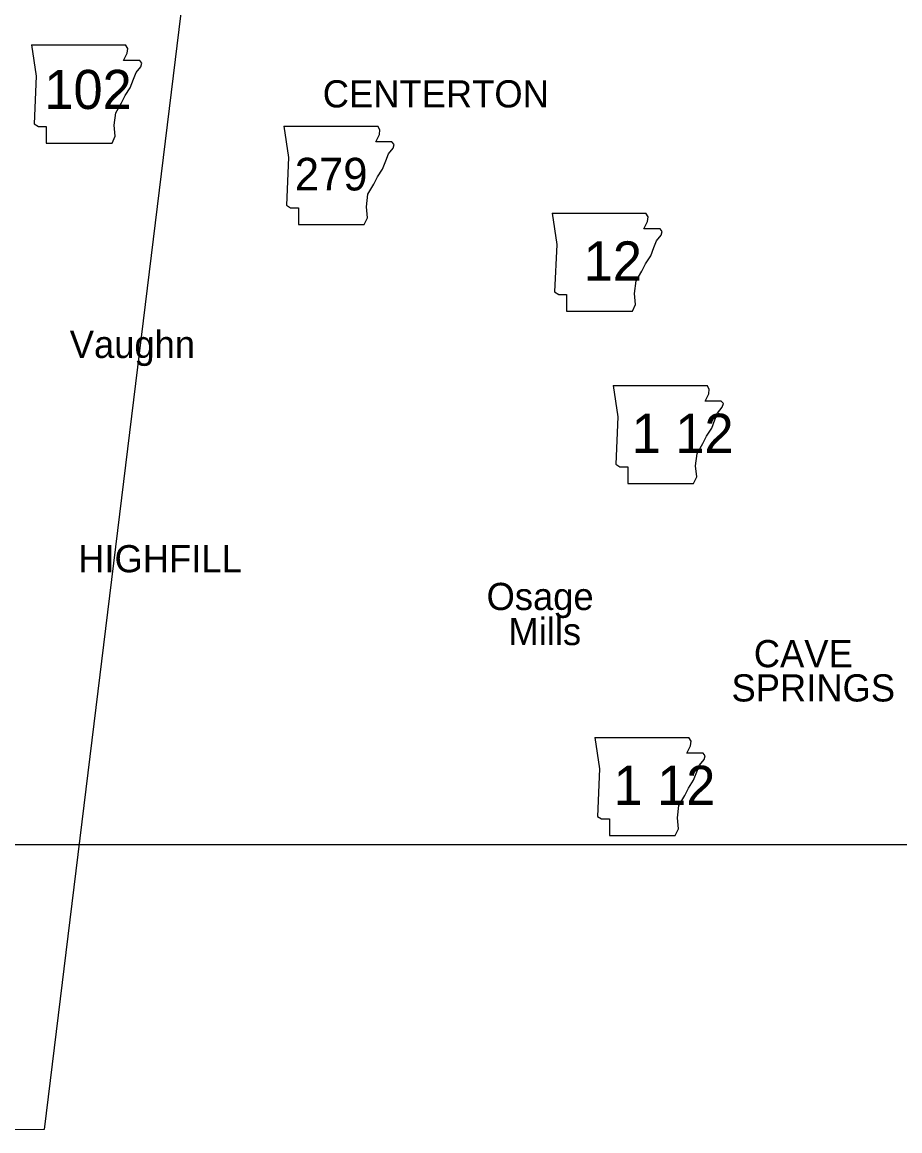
# Model space of a CAD drawing. Extents: x 6028647 to 6035072, y 5366486 to 5368495.
# Drawn here: x 6028934.9 to 6029148, y 5367846.9 to 5368116.1 of the extents above; entities that cross this region are included whole.
import ezdxf

# ---------------------------------------------------------------- set-up
doc = ezdxf.new("R2010")
doc.units = 0
for name, color, linetype in [('21', 7, 'Continuous'), ('24', 7, 'Continuous'), ('25', 7, 'Continuous'), ('Default', 7, 'Continuous'), ('R_NoPlot', 7, 'Continuous')]:
    doc.layers.add(name, color=color, linetype=linetype)

msp = doc.modelspace()

# ---------------------------------------------------------------- linework, layer by layer
at = {"layer": '21'}
for p, q in [((6028937.17, 5368110.57), (6028938.32, 5368102.95)), ((6028960.52, 5368109.68), (6028960, 5368110.56)), ((6028959.51, 5368106.76), (6028960.39, 5368108.54)), ((6028960.39, 5368108.54), (6028960.52, 5368109.68)), ((6028963.44, 5368106.76), (6028959.51, 5368106.76)), ((6028962.55, 5368103.84), (6028963.69, 5368105.24)), ((6028963.95, 5368106.13), (6028963.44, 5368106.76)), ((6028963.69, 5368105.24), (6028963.95, 5368106.13)), ((6028938.32, 5368102.95), (6028937.81, 5368091.41)), ((6028961.16, 5368100.16), (6028961.92, 5368102.19)), ((6028961.92, 5368102.19), (6028962.55, 5368103.84)), ((6028959.89, 5368098.26), (6028961.16, 5368100.16)), ((6028957.6, 5368094.07), (6028959, 5368096.48)), ((6028959, 5368096.48), (6028959.89, 5368098.26)), ((6028957.22, 5368091.03), (6028957.6, 5368094.07)), ((6028937.81, 5368091.41), (6028938.82, 5368090.77)), ((6028957.48, 5368088.36), (6028957.22, 5368091.03)), ((6028938.82, 5368090.77), (6028940.73, 5368090.77)), ((6028940.73, 5368090.77), (6028940.73, 5368086.71)), ((6028956.71, 5368086.71), (6028957.48, 5368088.36)), ((6028998.44, 5368090.8), (6028999.58, 5368083.19)), ((6029020.77, 5368087), (6029021.66, 5368088.77)), ((6029021.78, 5368089.91), (6029021.26, 5368090.79)), ((6029021.66, 5368088.77), (6029021.78, 5368089.91)), ((6028940.73, 5368086.71), (6028956.71, 5368086.71)), ((6029024.7, 5368087), (6029020.77, 5368087)), ((6029025.21, 5368086.36), (6029024.7, 5368087)), ((6029024.96, 5368085.47), (6029025.21, 5368086.36)), ((6028999.58, 5368083.19), (6028999.07, 5368071.64)), ((6029023.18, 5368082.43), (6029023.82, 5368084.08)), ((6029023.82, 5368084.08), (6029024.96, 5368085.47)), ((6029021.15, 5368078.49), (6029022.42, 5368080.4)), ((6029022.42, 5368080.4), (6029023.18, 5368082.43)), ((6029020.26, 5368076.72), (6029021.15, 5368078.49)), ((6029018.87, 5368074.31), (6029020.26, 5368076.72)), ((6029018.49, 5368071.26), (6029018.87, 5368074.31)), ((6028999.07, 5368071.64), (6029000.09, 5368071.01)), ((6029000.09, 5368071.01), (6029001.99, 5368071.01)), ((6029001.99, 5368071.01), (6029001.99, 5368066.95)), ((6029018.74, 5368068.6), (6029018.49, 5368071.26)), ((6029063.57, 5368069.72), (6029064.71, 5368062.11)), ((6029086.92, 5368068.83), (6029086.39, 5368069.71)), ((6029001.99, 5368066.95), (6029017.98, 5368066.95)), ((6029017.98, 5368066.95), (6029018.74, 5368068.6)), ((6029085.9, 5368065.91), (6029086.79, 5368067.69)), ((6029086.79, 5368067.69), (6029086.92, 5368068.83)), ((6029089.84, 5368065.91), (6029085.9, 5368065.91)), ((6029088.95, 5368063), (6029090.09, 5368064.39)), ((6029090.35, 5368065.28), (6029089.84, 5368065.91)), ((6029090.09, 5368064.39), (6029090.35, 5368065.28)), ((6029064.71, 5368062.11), (6029064.21, 5368050.56)), ((6029088.31, 5368061.35), (6029088.95, 5368063)), ((6029086.28, 5368057.41), (6029087.55, 5368059.32)), ((6029087.55, 5368059.32), (6029088.31, 5368061.35)), ((6029085.4, 5368055.64), (6029086.28, 5368057.41)), ((6029084, 5368053.23), (6029085.4, 5368055.64)), ((6029083.62, 5368050.18), (6029084, 5368053.23)), ((6029064.21, 5368050.56), (6029065.22, 5368049.93)), ((6029065.22, 5368049.93), (6029067.13, 5368049.93)), ((6029067.13, 5368049.93), (6029067.13, 5368045.87)), ((6029083.87, 5368047.52), (6029083.62, 5368050.18)), ((6029067.13, 5368045.87), (6029083.11, 5368045.87)), ((6029083.11, 5368045.87), (6029083.87, 5368047.52)), ((6029078.4, 5368027.89), (6029079.55, 5368020.27)), ((6029101.75, 5368027), (6029101.22, 5368027.88)), ((6029101.62, 5368025.86), (6029101.75, 5368027)), ((6029100.74, 5368024.08), (6029101.62, 5368025.86)), ((6029104.67, 5368024.08), (6029100.74, 5368024.08)), ((6029105.18, 5368023.45), (6029104.67, 5368024.08)), ((6029103.15, 5368019.51), (6029103.78, 5368021.16)), ((6029103.78, 5368021.16), (6029104.92, 5368022.56)), ((6029104.92, 5368022.56), (6029105.18, 5368023.45)), ((6029079.55, 5368020.27), (6029079.04, 5368008.73)), ((6029102.39, 5368017.48), (6029103.15, 5368019.51)), ((6029101.12, 5368015.58), (6029102.39, 5368017.48)), ((6029098.83, 5368011.39), (6029100.23, 5368013.8)), ((6029100.23, 5368013.8), (6029101.12, 5368015.58)), ((6029098.45, 5368008.35), (6029098.83, 5368011.39)), ((6029079.04, 5368008.73), (6029080.05, 5368008.09)), ((6029080.05, 5368008.09), (6029081.96, 5368008.09)), ((6029081.96, 5368008.09), (6029081.96, 5368004.03)), ((6029098.71, 5368005.68), (6029098.45, 5368008.35)), ((6029097.94, 5368004.03), (6029098.71, 5368005.68)), ((6029081.96, 5368004.03), (6029097.94, 5368004.03)), ((6029073.98, 5367942.43), (6029075.12, 5367934.82)), ((6029096.31, 5367938.62), (6029097.2, 5367940.4)), ((6029097.33, 5367941.54), (6029096.8, 5367942.42)), ((6029097.2, 5367940.4), (6029097.33, 5367941.54)), ((6029100.25, 5367938.62), (6029096.31, 5367938.62)), ((6029100.75, 5367937.99), (6029100.25, 5367938.62)), ((6029100.5, 5367937.1), (6029100.75, 5367937.99)), ((6029098.72, 5367934.06), (6029099.36, 5367935.71)), ((6029099.36, 5367935.71), (6029100.5, 5367937.1)), ((6029075.12, 5367934.82), (6029074.62, 5367923.27)), ((6029097.96, 5367932.03), (6029098.72, 5367934.06)), ((6029095.81, 5367928.35), (6029096.69, 5367930.12)), ((6029096.69, 5367930.12), (6029097.96, 5367932.03)), ((6029094.41, 5367925.94), (6029095.81, 5367928.35)), ((6029094.03, 5367922.89), (6029094.41, 5367925.94)), ((6029074.62, 5367923.27), (6029075.63, 5367922.64)), ((6029075.63, 5367922.64), (6029077.53, 5367922.64)), ((6029077.53, 5367922.64), (6029077.53, 5367918.58)), ((6029094.28, 5367920.23), (6029094.03, 5367922.89)), ((6029093.52, 5367918.58), (6029094.28, 5367920.23)), ((6029077.53, 5367918.58), (6029093.52, 5367918.58))]:
    msp.add_line(p, q, dxfattribs=at)
for points in [[(6028937.17, 5368110.57), (6028960, 5368110.56)], [(6028998.44, 5368090.8), (6029021.26, 5368090.79)], [(6029063.57, 5368069.72), (6029086.39, 5368069.71)], [(6029078.4, 5368027.89), (6029101.22, 5368027.88)], [(6029073.98, 5367942.43), (6029096.8, 5367942.42)]]:
    msp.add_lwpolyline(points, dxfattribs=at)
at = {"layer": 'Default'}
msp.add_lwpolyline([(6028985.94, 5368220.75), (6028940.2, 5367847.26), (6028659.63, 5367846.93)], dxfattribs=at)
at = {"layer": 'R_NoPlot'}
msp.add_lwpolyline([(6028702.18, 5368445.48), (6029287.88, 5368445.48), (6029287.88, 5367916.32), (6028702.18, 5367916.32)], close=True, dxfattribs=at)

# ---------------------------------------------------------------- texts
at = {"layer": '21'}
for s, height, p in [('102', 9.504, (6028940.29, 5368094.98)), ('279', 7.92, (6029001.1, 5368075.21)), ('12', 9.504, (6029071.28, 5368053.34)), ('1 12', 9.504, (6029082.93, 5368011.51)), ('1 12', 9.504, (6029078.51, 5367926.05))]:
    msp.add_text(s, height=height, dxfattribs=at).set_placement(p)
at = {"layer": '24'}
msp.add_text('Vaughn', height=6.6, dxfattribs=at).set_placement((6028946.45, 5368034.54))
at = {"layer": '25'}
for s, p in [('CENTERTON', (6029007.89, 5368095.36)), ('HIGHFILL', (6028948.5, 5367982.51)), ('Osage', (6029047.68, 5367973.35)), ('Mills', (6029053, 5367964.84)), ('CAVE', (6029112.58, 5367959.47)), ('SPRINGS', (6029107.16, 5367951.15))]:
    msp.add_text(s, height=6.6, dxfattribs=at).set_placement(p)

doc.saveas('drawing.dxf')
